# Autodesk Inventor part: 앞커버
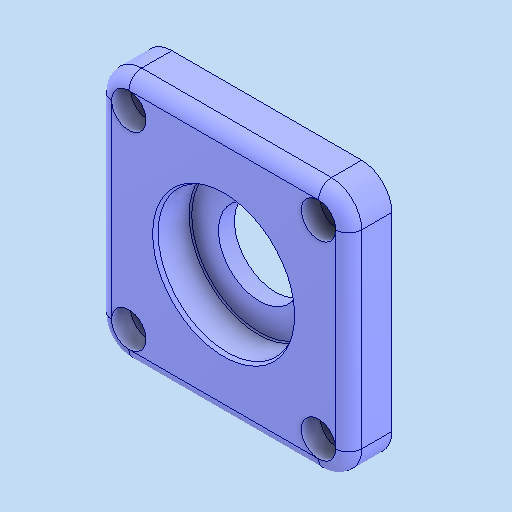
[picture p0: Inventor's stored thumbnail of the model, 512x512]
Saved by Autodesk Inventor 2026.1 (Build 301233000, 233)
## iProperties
Created: 2026-01
Part Number: 앞커버
Material: 알루미늄 6061
Document SubType Name: Modeling
Designer: PC-30
Density: 2.7 g/cm^3
Appearance: 기본값
Author: jhkim
Sending System: Autodesk Inventor 2026
Preprocessor: ST-DEVELOPER v20.1
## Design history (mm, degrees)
feature "솔리드1"
node "솔리드2"
